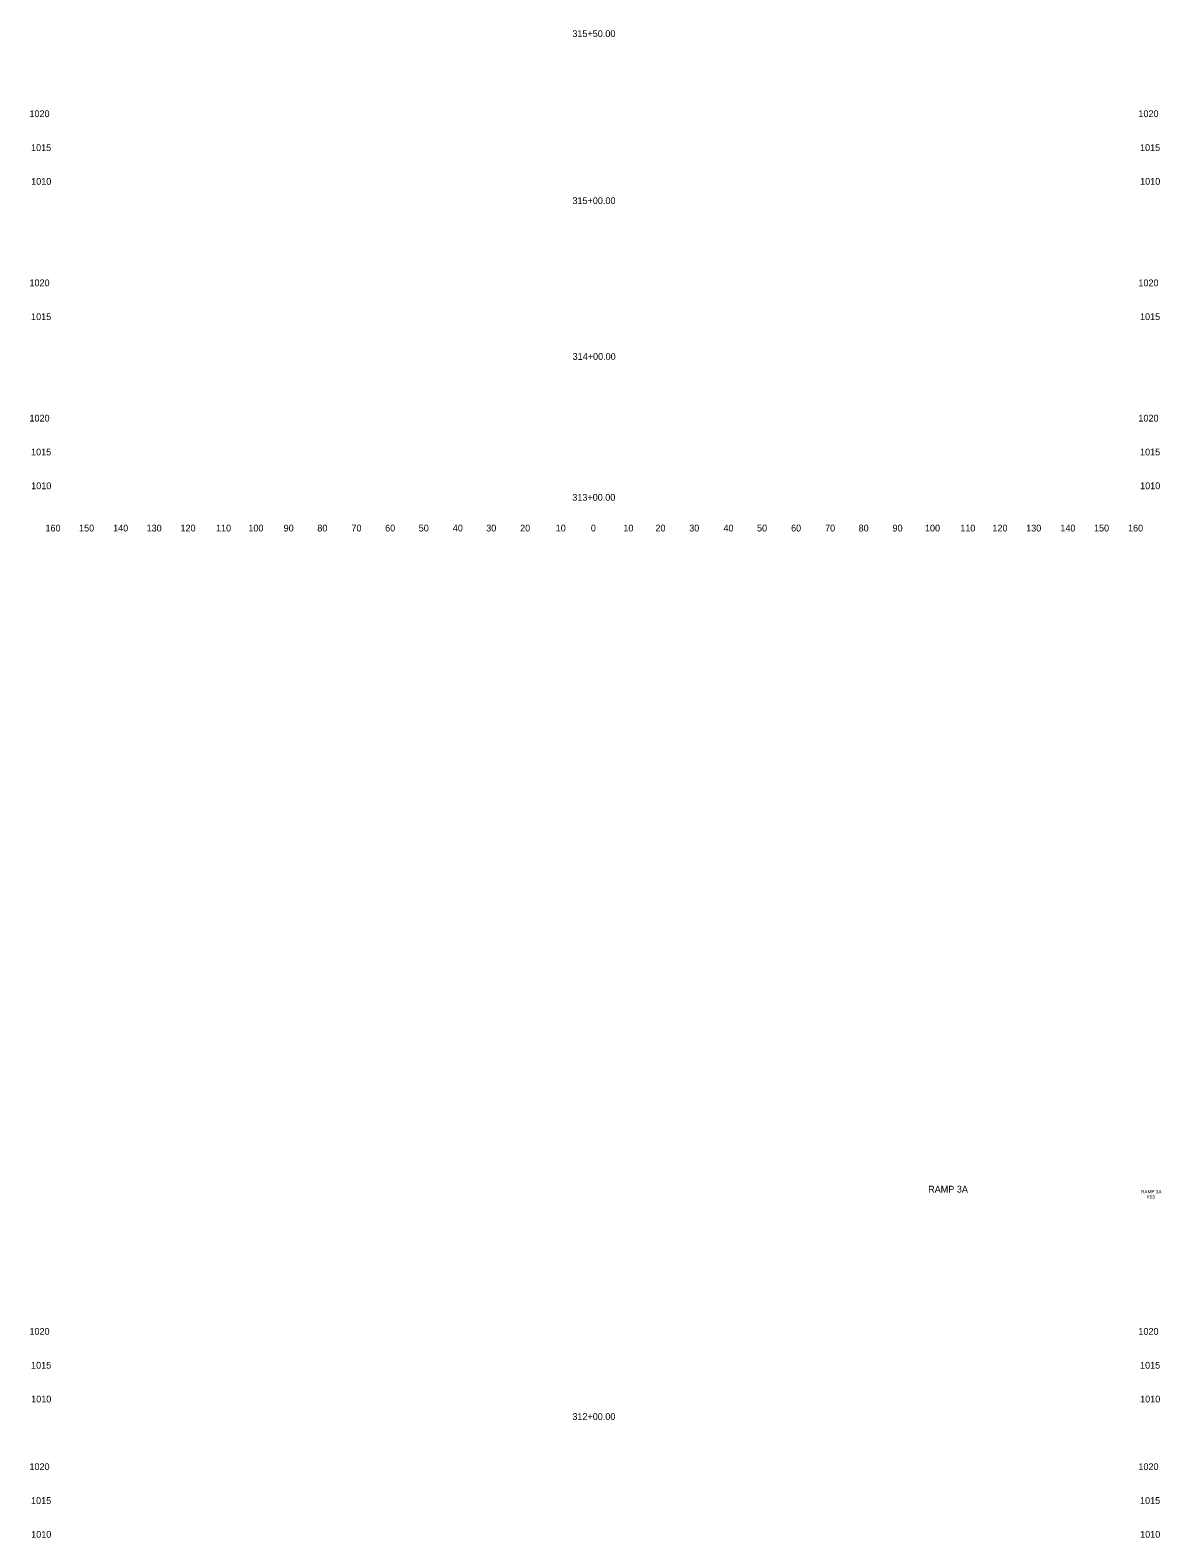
# Model space of a CAD drawing. Extents: x 4286 to 5843, y 4997 to 8804.
# Drawn here: x 5508.6 to 5842.8, y 5900 to 6345.7 of the extents above; entities that cross this region are included whole.
import ezdxf

# ---------------------------------------------------------------- set-up
doc = ezdxf.new("R2010")
doc.units = 0
for name, color, linetype in [('RD_SHT_ID', 7, 'Continuous'), ('RD_XS_TX_Offset', 7, 'Continuous'), ('RD_XS_TX_Station', 7, 'Continuous')]:
    doc.layers.add(name, color=color, linetype=linetype)

msp = doc.modelspace()

# ---------------------------------------------------------------- texts
at = {"layer": 'RD_SHT_ID'}
for s, height, p in [('RAMP 3A', 2, (5774.02, 6002.06)), ('RAMP 3A', 1, (5836.93, 6001.8)), ('X13', 1, (5838.57, 6000.3))]:
    msp.add_text(s, height=height, dxfattribs=at).set_placement(p)
at = {"layer": 'RD_XS_TX_Offset'}
for s, p in [('1020', (5508.37, 6320)), ('1020', (5836.17, 6320)), ('1015', (5508.85, 6310)), ('1015', (5836.65, 6310)), ('1010', (5508.88, 6300)), ('1010', (5836.68, 6300)), ('1020', (5508.37, 6270)), ('1020', (5836.17, 6270)), ('1015', (5508.85, 6260)), ('1015', (5836.65, 6260)), ('1020', (5508.37, 6230)), ('1020', (5836.17, 6230)), ('1015', (5508.85, 6220)), ('1015', (5836.65, 6220)), ('1010', (5508.88, 6210)), ('1010', (5836.68, 6210)), ('160', (5513.1, 6197.5)), ('150', (5523.04, 6197.5)), ('140', (5533.1, 6197.5)), ('130', (5542.99, 6197.5)), ('120', (5553.01, 6197.5)), ('110', (5563.51, 6197.5)), ('100', (5573.07, 6197.5)), ('90', (5583.5, 6197.5)), ('80', (5593.46, 6197.5)), ('70', (5603.54, 6197.5)), ('60', (5613.5, 6197.5)), ('50', (5623.43, 6197.5)), ('40', (5633.5, 6197.5)), ('30', (5643.39, 6197.5)), ('20', (5653.4, 6197.5)), ('10', (5663.91, 6197.5)), ('0', (5674.3, 6197.5)), ('0', (5674.3, 6197.5)), ('10', (5683.91, 6197.5)), ('20', (5693.4, 6197.5)), ('30', (5703.39, 6197.5)), ('40', (5713.5, 6197.5)), ('50', (5723.43, 6197.5)), ('60', (5733.5, 6197.5)), ('70', (5743.54, 6197.5)), ('80', (5753.46, 6197.5)), ('90', (5763.5, 6197.5)), ('100', (5773.07, 6197.5)), ('110', (5783.51, 6197.5)), ('120', (5793.01, 6197.5)), ('130', (5802.99, 6197.5)), ('140', (5813.1, 6197.5)), ('150', (5823.04, 6197.5)), ('160', (5833.1, 6197.5)), ('1020', (5508.37, 5960)), ('1020', (5836.17, 5960)), ('1015', (5508.85, 5950)), ('1015', (5836.65, 5950)), ('1010', (5508.88, 5940)), ('1010', (5836.68, 5940)), ('1020', (5508.37, 5920)), ('1020', (5836.17, 5920)), ('1015', (5508.85, 5910)), ('1015', (5836.65, 5910)), ('1010', (5508.88, 5900)), ('1010', (5836.68, 5900))]:
    msp.add_text(s, height=2, dxfattribs=at).set_placement(p)
at = {"layer": 'RD_XS_TX_Station'}
for s, p in [('315+50.00', (5668.85, 6343.68)), ('315+00.00', (5668.88, 6294.3)), ('314+00.00', (5668.94, 6248.23)), ('313+00.00', (5668.83, 6206.59)), ('312+00.00', (5668.85, 5934.83))]:
    msp.add_text(s, height=2, dxfattribs=at).set_placement(p)

doc.saveas('drawing.dxf')
